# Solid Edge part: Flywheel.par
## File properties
Author: there
Template: Iso Metric Part.par
Last saved by: there
Revision: 14
Application: Solid Edge
Precisión: 0.990
Username: there
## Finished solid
Body 1: solid body, 45 faces, 122 edges, 72 vertices.
  Faces by surface: cylinder 31, plane 14
  Edges by curve: circle 62, line 60
Bounding box of the edges (mm): 101.503 x 1.950 x 112.450, from (-50.6517, -3.354, -56.2247) to (50.8513, -1.404, 56.225).
Cylindrical faces by radius (mm): R4.16 x1, R8.45 x6, R10.4 x6, R14.625 x6, R31.2 x6, R41.6 x6
Planar faces by outward normal: +x 2, +y 1, -x 2, -y 1, oblique 8
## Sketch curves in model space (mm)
arc centre (0.1828, -2.16, -49.9997) radius 13.081 from (-3.1989, -2.16, -37.3633) through (-3.0887, -2.16, -37.3343) to (-2.9783, -2.16, -37.3063)
arc centre (0.1828, -2.16, -49.9997) radius 13.081 from (2.9783, -2.16, -37.2208) through (3.2257, -2.16, -37.2775) to (3.472, -2.16, -37.3389)
arc centre (-43.1994, -2.16, 25.1756) radius 13.0129 from (-30.7105, -2.16, 21.5201) through (-30.7551, -2.16, 21.3709) to (-30.8015, -2.16, 21.2224)
arc centre (0, -2.16, 50) radius 13.0052 from (3.1059, -2.16, 37.3712) through (3.0433, -2.16, 37.3559) to (2.9805, -2.16, 37.341)
arc centre (43.5412, -2.16, -24.5797) radius 13.0826 from (33.6664, -2.16, -15.9982) through (33.9134, -2.16, -15.7221) to (34.168, -2.16, -15.453)
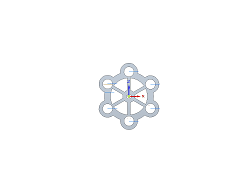
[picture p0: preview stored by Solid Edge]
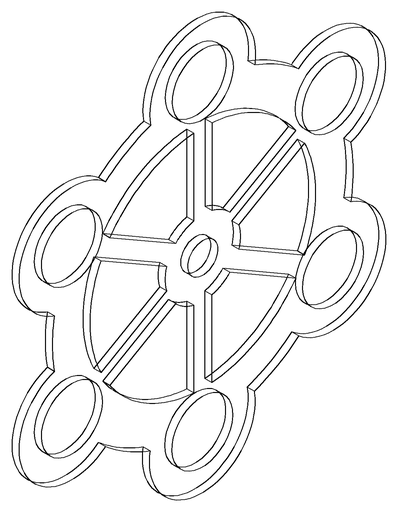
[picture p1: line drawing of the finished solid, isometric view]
